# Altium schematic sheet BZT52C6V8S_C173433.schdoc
size 127 x 101 mm
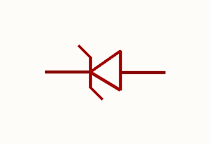
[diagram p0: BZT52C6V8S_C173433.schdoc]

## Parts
D?  bzt52c6v8s_c173433  [SOD-323_L1.8-W1.3-LS2.5-RD]  (value not drawn)

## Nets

Not connected (* = marked no-connect by the designer): D? 1 2

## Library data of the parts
D? = bzt52c6v8s_c173433: 二极管配置:1个独立式;稳压值(标称值):6.8V;稳压值(范围):6.4V~7.2V;耗散功率(Pd):200mW;; Manufacturer: MDD(辰达半导体); AddInBom: yes; ModelId: db63db13d9e342eb939127d413d6200b; ModelTransform: 104.3305,51.181,0,0,0,0,0,-0.004,0; Diode Configuration: 1个独立式; Zener Voltage(Nom): 6.8V; Reverse Leakage Current (Ir): 500nA; Pd - Power Dissipation: 200mW; Impedance(Zzt): 30Ω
